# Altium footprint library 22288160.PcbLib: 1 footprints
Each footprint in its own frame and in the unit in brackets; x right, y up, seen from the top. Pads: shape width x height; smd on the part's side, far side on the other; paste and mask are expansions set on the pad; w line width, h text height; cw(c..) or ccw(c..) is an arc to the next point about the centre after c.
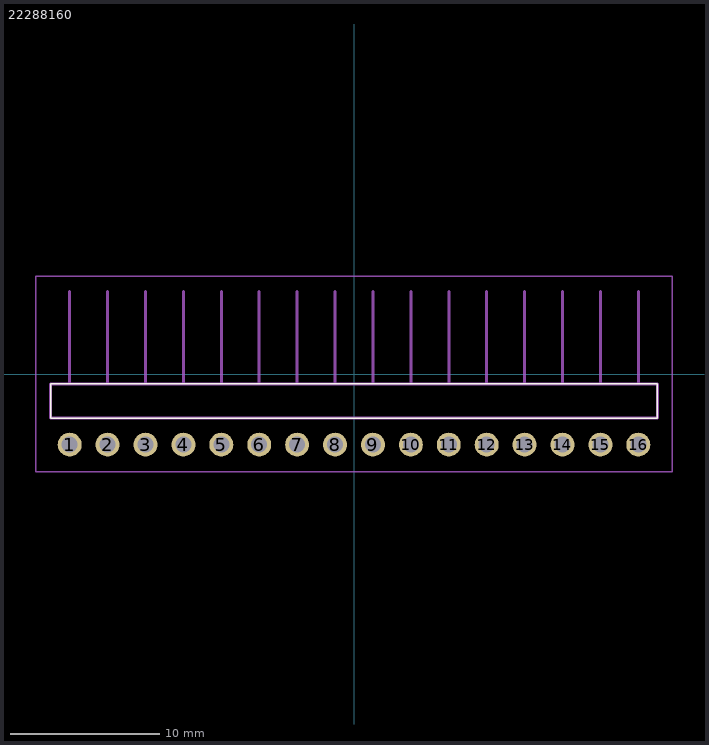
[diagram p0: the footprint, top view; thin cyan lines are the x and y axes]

## 22288160 [mm]
pads (16):
  round 1.605 hole 1.07: 1(-19.05,-4.734) 2(-16.51,-4.734) 3(-13.97,-4.734) 4(-11.43,-4.734) 5(-8.89,-4.734) 6(-6.35,-4.734) 7(-3.81,-4.734) 8(-1.27,-4.734) 9(1.27,-4.734) 10(3.81,-4.734) 11(6.35,-4.734) 12(8.89,-4.734) 13(11.43,-4.734) 14(13.97,-4.734) 15(16.51,-4.734) 16(19.05,-4.734)
Top Overlay:
  lines w0.1: -20.32,-2.954 20.32,-2.954 20.32,-0.664 -20.32,-0.664 -20.32,-2.954
Mechanical 15:
  lines w0.2: -19.05,-0.664 -19.05,5.536 ; -16.51,-0.664 -16.51,5.536 ; -13.97,-0.664 -13.97,5.536 ; -11.43,-0.664 -11.43,5.536 ; -8.89,-0.664 -8.89,5.536 ; -6.35,-0.664 -6.35,5.536 ; -3.81,-0.664 -3.81,5.536 ; -1.27,-0.664 -1.27,5.536 ; 1.27,-0.664 1.27,5.536 ; 3.81,-0.664 3.81,5.536 ; 6.35,-0.664 6.35,5.536 ; 8.89,-0.664 8.89,5.536 ; 11.43,-0.664 11.43,5.536 ; 13.97,-0.664 13.97,5.536 ; 16.51,-0.664 16.51,5.536 ; 19.05,-0.664 19.05,5.536 ; -20.32,-2.954 20.32,-2.954 20.32,-0.664 -20.32,-0.664 -20.32,-2.954
Mechanical 20:
  lines w0.1: -21.32,-6.536 21.32,-6.536 21.32,6.536 -21.32,6.536 -21.32,-6.536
